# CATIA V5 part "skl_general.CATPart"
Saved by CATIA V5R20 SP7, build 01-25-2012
Part number: skl_general
Publications: "longueur_1", "A", "B", "C", "D", "E", "F", "G", "Plan.1", "H", "symG", "Ratio_point_ellipse"
Bounding box of the stored display mesh (mm): x 0 to 0, y -70.711 to 50, z 0 to 173.205
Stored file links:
  G:\bon\Nouveau dossier\skl_general.CATPart
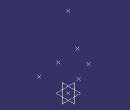
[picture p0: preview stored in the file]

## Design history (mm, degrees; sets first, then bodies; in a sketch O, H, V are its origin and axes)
Parameters
  longueur_1 = 100 mm
  Ratio_point_ellipse = 0.8
Set1
  Sketch1 on yz-plane, origin (0, 0, 0), H (0, 1, 0), V (0, 0, 1)
    point P1 (0, 0)
    line L1 through (0, 0) direction (1, 0)
    circle A1 centre (0, 0) radius 70.7107
    point P4 (-70.7107, 0)
    point P5 (70.7107, 0)
    circle A2 centre (0, 0) radius 100
    point P6 (50, 86.6025)
    line L2 (0, 0) -> (50, 86.6025)
    point P7 (-35.3553, -61.2372)
    circle A3 centre (-70.7107, 0) radius 70.7107
    circle A4 centre (0, 0) radius 50
    point P8 (25, 43.3013)
    point P9 (-25, -43.3013)
    circle A5 centre (25, 43.3013) radius 50
    point P10 (-24.0283, 53.1108)
    point P11 (0, 0)
    line L3 (-70.7107, 0) -> (-24.0283, 53.1108)
    circle A6 centre (-70.7107, 0) radius 141.4214
    point P12 (22.6541, 106.2216)
    line L4 (-24.0283, 53.1108) -> (22.6541, 106.2216)
    line L5 (25, 43.3013) -> (-24.0283, 53.1108)
    circle A7 centre (50, 86.6025) radius 100
    circle A8 centre (22.6541, 106.2216) radius 70.7107
    point P13 (0, 173.2051)
    point P14 (-48.0566, 106.2216)
    line L6 (50, 86.6025) -> (0, 173.2051)
    line L7 (22.6541, 106.2216) -> (0, 173.2051)
    point P15 (75, 43.3013)
    point P16 (75, 43.3013)
    point P17 (75, 43.3013)
    distance O A1 = 70.7107 {= longueur_1/sqrt(2)}
    distance O A2 = 100 {= longueur_1}
    distance P4 A3 = 70.7107 {= longueur_1/sqrt(2)}
    distance O A4 = 50 {= longueur_1/2}
    distance P8 A5 = 50 {= longueur_1/2}
    distance P4 A6 = 141.4214 {= longueur_1*sqrt(2)}
    distance P6 A7 = 100 {= longueur_1}
    distance P12 A8 = 70.7107 {= longueur_1/sqrt(2)}
    coincidence: P1 O, L1 O, A1 P4, L1 P4, A1 P5, L1 P5, P6 A2, L2 P7, A1 P7, A3 P7, A4 P8, L2 P8, A4 P9, L2 P9, A5 P10, A3 P10, A5 P11, A3 P11, P12 A6, P12 L3, A8 P13, A7 P13, A8 P14, A7 P14, L6 P15, L6 P16, L6 P17
    horizontal: L1 H
    parallelism: L4 L3
  Point1 "A": (0, 0, 0), relative to Sketch1.P11
  Point2 "B": (0, 0, 0), relative to vertex [element of Sketch1 | element of Sketch1]
  Point3 "C": (0, 0, 0), relative to vertex [element of Sketch1 | element of Sketch1]
  Point4 "D": (0, 0, 0), relative to Sketch1.P10
  Point5 "E": (0, 0, 0), relative to Sketch1.P8
  Point6 "F": (0, 0, 0), relative to vertex [element of Sketch1 | element of Sketch1]
  Point7 "G": (0, 0, 0), relative to Sketch1.P4
  Plane1: type Offset, RefPlane yz-plane, Offset 0
  Point8 "H": (0, 0, 152 {= 1.52*longueur_1})
  Point9 "symG": (0, 70.7107 {= longueur_1/sqrt(2)}, 0)
Body1 (main body)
